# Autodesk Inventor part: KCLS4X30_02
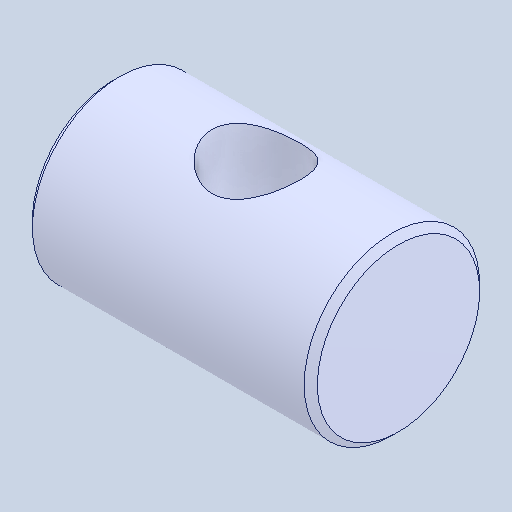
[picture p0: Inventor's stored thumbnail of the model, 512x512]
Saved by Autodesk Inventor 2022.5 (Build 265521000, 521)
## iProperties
Created: 2024-08
Part Number: KCLS4X30_02
Material: 一般
Document SubType Name: Modeling
Designer: ImaoCorp
Density: 1 g/cm^3
Appearance: 既定
Author: ImaoCorp
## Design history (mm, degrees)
feature "KCLS4X30_02"
node "ソリッド1"
